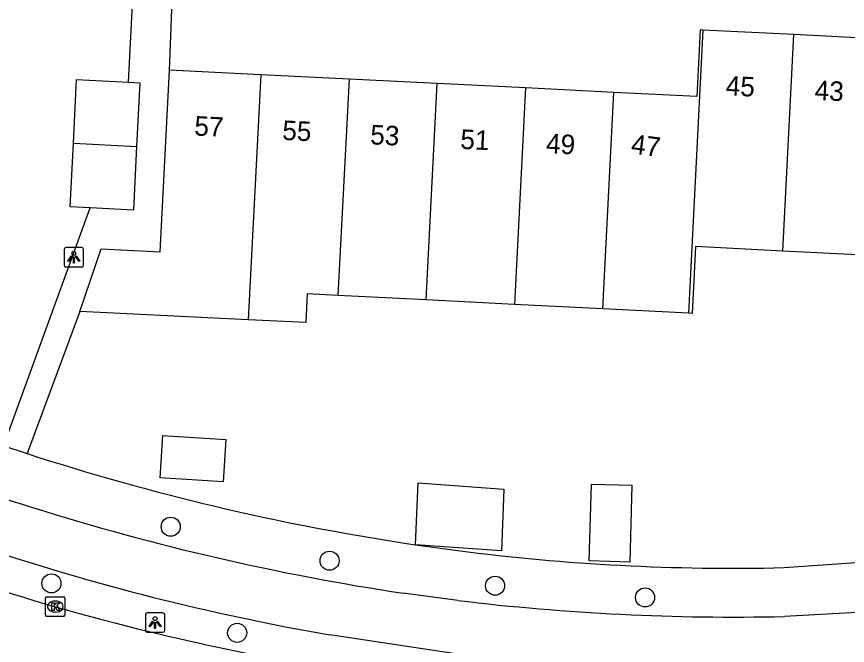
# Model space of a CAD drawing. Extents: x 162990 to 165007, y 383433 to 384336.
# Drawn here: x 164477.39 to 164519.96, y 383514.29 to 383546.51 of the extents above; entities that cross this region are included whole.
import ezdxf

# ---------------------------------------------------------------- set-up
doc = ezdxf.new("R2010")
doc.units = 0
for name, color, linetype in [('IMGEO_Boom', 7, 'Continuous'), ('IMGEO_Fietspad_open', 7, 'Continuous'), ('IMGEO_Kolk', 7, 'Continuous'), ('IMGEO_Lichtpunt', 7, 'Continuous'), ('IMGEO_Pand', 7, 'Continuous'), ('IMGEO_Pand_nummerreeks', 7, 'Continuous'), ('IMGEO_Rijbaan_lokaal_open', 7, 'Continuous'), ('IMGEO_Voetpad_open', 7, 'Continuous')]:
    doc.layers.add(name, color=color, linetype=linetype)

msp = doc.modelspace()

# ---------------------------------------------------------------- linework, layer by layer
at = {"layer": 'IMGEO_Boom'}
for centre in [(164485.284, 383520.372), (164493.424, 383518.629), (164479.172, 383517.468), (164501.908, 383517.349), (164509.595, 383516.747), (164488.689, 383514.935)]:
    msp.add_circle(centre, 0.489, dxfattribs=at)
at = {"layer": 'IMGEO_Fietspad_open'}
for points in [[(164542.439, 383519.028), (164533.777, 383517.315), (164523.876, 383516.16), (164516.744, 383515.769)], [(164500, 383516.592), (164497.201, 383516.963)], [(164502.731, 383513.509), (164500, 383513.845), (164493.44, 383514.828)]]:
    msp.add_lwpolyline(points, dxfattribs=at)
for centre, radius, start, end in [((164514.283, 383636.128), 120.309, 243.49407, 252.56886), ((164516.002, 383641.528), 125.976, 252.55873, 261.41717), ((164514.674, 383636.728), 123.736, 251.50092, 260.11867), ((164514.174, 383634.22), 118.479, 263.12914, 271.24299)]:
    msp.add_arc(centre, radius, start, end, dxfattribs=at)
at = {"layer": 'IMGEO_Kolk'}
for p, q in [((164478.864, 383515.852), (164478.864, 383516.704)), ((164478.939, 383516.778), (164479.791, 383516.778)), ((164479.352, 383516.558), (164479.377, 383516.558)), ((164479.865, 383516.704), (164479.865, 383515.852)), ((164479.791, 383515.778), (164478.939, 383515.778)), ((164479.375, 383515.998), (164479.35, 383515.998))]:
    msp.add_line(p, q, dxfattribs=at)
for points in [[(164478.864, 383515.852), (164478.864, 383516.704)], [(164478.939, 383516.778), (164479.791, 383516.778)], [(164479.865, 383516.704), (164479.865, 383515.852)], [(164479.185, 383516.478), (164479.308, 383516.478), (164479.308, 383516.327), (164479.438, 383516.478), (164479.602, 383516.478), (164479.456, 383516.327), (164479.609, 383516.078), (164479.457, 383516.078), (164479.372, 383516.242), (164479.308, 383516.175), (164479.308, 383516.078), (164479.185, 383516.078), (164479.185, 383516.478)], [(164479.791, 383515.778), (164478.939, 383515.778)]]:
    msp.add_lwpolyline(points, dxfattribs=at)
for centre, start, end in [((164478.941, 383516.702), 91.552, 178.448), ((164478.941, 383516.702), 91.552, 178.448), ((164479.789, 383516.702), 1.552, 88.448), ((164479.789, 383516.702), 1.552, 88.448), ((164478.941, 383515.854), 181.552, 268.448), ((164478.941, 383515.854), 181.552, 268.448), ((164479.789, 383515.854), 271.552, 358.448), ((164479.789, 383515.854), 271.552, 358.448)]:
    msp.add_arc(centre, 0.0765, start, end, dxfattribs=at)
for centre, major_axis, ratio, start_param, end_param in [((164479.351, 383516.278), (-0.387, 0.002), 0.722429, 4.712389, 7.853982), ((164479.376, 383516.278), (-0.39, 0.002), 0.717154, 1.570796, 4.712389)]:
    msp.add_ellipse(centre, major_axis=major_axis, ratio=ratio, start_param=start_param, end_param=end_param, dxfattribs=at)
at = {"layer": 'IMGEO_Lichtpunt'}
for p, q in [((164479.821, 383534.583), (164479.821, 383533.776)), ((164479.821, 383534.583), (164479.821, 383533.776)), ((164480.723, 383534.678), (164479.915, 383534.678)), ((164480.723, 383534.678), (164479.915, 383534.678)), ((164480.817, 383533.776), (164480.817, 383534.583)), ((164480.817, 383533.776), (164480.817, 383534.583)), ((164479.915, 383533.682), (164480.723, 383533.682)), ((164479.915, 383533.682), (164480.723, 383533.682)), ((164483.985, 383515.865), (164483.985, 383515.058)), ((164483.985, 383515.865), (164483.985, 383515.058)), ((164484.887, 383515.96), (164484.079, 383515.96)), ((164484.887, 383515.96), (164484.079, 383515.96)), ((164484.981, 383515.058), (164484.981, 383515.865)), ((164484.981, 383515.058), (164484.981, 383515.865)), ((164484.079, 383514.964), (164484.887, 383514.964)), ((164484.079, 383514.964), (164484.887, 383514.964))]:
    msp.add_line(p, q, dxfattribs=at)
for points in [[(164480.195, 383534.247), (164480.234, 383534.219), (164480.046, 383533.957), (164480.008, 383533.984), (164480.195, 383534.247)], [(164480.297, 383534.199), (164480.344, 383534.199), (164480.344, 383533.877), (164480.297, 383533.877), (164480.297, 383534.199)], [(164480.407, 383534.219), (164480.445, 383534.246), (164480.632, 383533.984), (164480.593, 383533.956), (164480.407, 383534.219)], [(164484.359, 383515.529), (164484.398, 383515.501), (164484.21, 383515.239), (164484.172, 383515.266), (164484.359, 383515.529)], [(164484.461, 383515.481), (164484.508, 383515.481), (164484.508, 383515.159), (164484.461, 383515.159), (164484.461, 383515.481)], [(164484.571, 383515.501), (164484.609, 383515.528), (164484.796, 383515.266), (164484.757, 383515.238), (164484.571, 383515.501)]]:
    msp.add_lwpolyline(points, dxfattribs=at)
for centre in [(164480.32, 383534.381), (164484.484, 383515.663)]:
    msp.add_circle(centre, 0.0994, dxfattribs=at)
for centre, start, end in [((164479.915, 383534.583), 90, 180), ((164479.915, 383534.583), 90, 180), ((164480.723, 383534.583), 0, 90), ((164480.723, 383534.583), 0, 90), ((164479.915, 383533.776), 180, 270), ((164479.915, 383533.776), 180, 270), ((164480.723, 383533.776), 270, 0), ((164480.723, 383533.776), 270, 360), ((164484.079, 383515.865), 90, 180), ((164484.079, 383515.865), 90, 180), ((164484.887, 383515.865), 0, 90), ((164484.887, 383515.865), 0, 90), ((164484.079, 383515.058), 180, 270), ((164484.079, 383515.058), 180, 270), ((164484.887, 383515.058), 270, 0), ((164484.887, 383515.058), 270, 360)]:
    msp.add_arc(centre, 0.0946, start, end, dxfattribs=at)
at = {"layer": 'IMGEO_Pand'}
for points in [[(164512.563, 383545.826), (164512.425, 383545.833), (164512.251, 383542.419), (164507.999, 383542.632)], [(164512.563, 383545.826), (164511.823, 383531.309)], [(164517.223, 383545.589), (164512.563, 383545.826)], [(164516.658, 383534.5), (164517.223, 383545.589)], [(164521.748, 383545.358), (164517.223, 383545.589)], [(164480.622, 383531.4), (164481.715, 383534.619), (164484.74, 383534.464), (164485.215, 383543.771)], [(164489.897, 383543.537), (164485.215, 383543.771)], [(164489.897, 383543.537), (164489.256, 383530.976)], [(164494.422, 383543.311), (164489.897, 383543.537)], [(164480.298, 383540.025), (164480.464, 383543.291), (164483.115, 383543.156)], [(164483.115, 383543.156), (164483.702, 383543.126), (164483.536, 383539.86)], [(164494.422, 383543.311), (164493.857, 383532.224)], [(164498.947, 383543.085), (164494.422, 383543.311)], [(164498.382, 383531.994), (164498.947, 383543.085)], [(164503.473, 383542.858), (164500, 383543.032), (164498.947, 383543.085)], [(164503.473, 383542.858), (164502.907, 383531.764)], [(164507.999, 383542.632), (164503.473, 383542.858)], [(164507.433, 383531.533), (164507.999, 383542.632)], [(164481.15, 383536.706), (164480.131, 383536.758), (164480.298, 383540.025)], [(164480.298, 383540.025), (164483.536, 383539.86)], [(164483.536, 383539.86), (164483.37, 383536.593), (164481.15, 383536.706)], [(164516.658, 383534.5), (164512.182, 383534.728), (164512.007, 383531.3), (164511.823, 383531.309)], [(164521.183, 383534.27), (164516.658, 383534.5)], [(164493.857, 383532.224), (164492.282, 383532.304), (164492.209, 383530.831), (164489.256, 383530.976)], [(164498.382, 383531.994), (164493.857, 383532.224)], [(164502.907, 383531.764), (164500, 383531.912), (164498.382, 383531.994)], [(164507.433, 383531.533), (164502.907, 383531.764)], [(164511.823, 383531.309), (164507.433, 383531.533)], [(164489.256, 383530.976), (164480.622, 383531.4)], [(164487.969, 383522.672), (164484.748, 383522.879), (164484.888, 383525.054), (164488.109, 383524.847), (164487.969, 383522.672)], [(164497.832, 383519.451), (164497.959, 383522.622), (164502.364, 383522.301), (164502.237, 383519.13), (164497.832, 383519.451)], [(164508.81, 383518.561), (164506.738, 383518.619), (164506.849, 383522.556), (164508.921, 383522.498), (164508.81, 383518.561)]]:
    msp.add_lwpolyline(points, dxfattribs=at)
at = {"layer": 'IMGEO_Rijbaan_lokaal_open'}
for centre, radius, start, end in [((164510.138, 383622.615), 110.704, 251.41515, 256.4377), ((164515.311, 383638.896), 132.838, 248.66828, 256.63848), ((164521.742, 383672.617), 162.033, 256.5953, 262.28873)]:
    msp.add_arc(centre, radius, start, end, dxfattribs=at)
at = {"layer": 'IMGEO_Voetpad_open'}
for points in [[(164483.115, 383543.156), (164484.342, 383566.747), (164474.157, 383567.244), (164474.064, 383565.291)], [(164485.215, 383543.771), (164485.409, 383548.65)], [(164476.724, 383524.524), (164476.8, 383524.732), (164481.15, 383536.706)], [(164480.622, 383531.4), (164477.932, 383524.118)], [(164476.724, 383524.524), (164477.932, 383524.118)], [(164516.716, 383518.274), (164525.09, 383518.868), (164529.601, 383519.271), (164538.692, 383520.777), (164542.258, 383521.655)], [(164497.376, 383519.515), (164497.832, 383519.451)], [(164497.832, 383519.451), (164500, 383519.146)]]:
    msp.add_lwpolyline(points, dxfattribs=at)
for centre, radius, start, end in [((164515.888, 383641.084), 122.971, 252.02138, 261.3416), ((164514.116, 383629.093), 110.849, 262.68376, 271.34392)]:
    msp.add_arc(centre, radius, start, end, dxfattribs=at)

# ---------------------------------------------------------------- texts
at = {"layer": 'IMGEO_Pand_nummerreeks'}
for s, rotation, p in [('45', 357.0849, (164513.711, 383542.484)), ('43', 357.0849, (164518.267, 383542.252)), ('57', 357.1372, (164486.479, 383540.424)), ('55', 357.1372, (164490.985, 383540.199)), ('53', 357.1372, (164495.491, 383539.973)), ('51', 357.1372, (164500.11, 383539.742)), ('49', 357.1372, (164504.503, 383539.523)), ('47', 352.875, (164508.838, 383539.504))]:
    msp.add_text(s, height=1, rotation=rotation, dxfattribs=at).set_placement(p)

doc.saveas('drawing.dxf')
